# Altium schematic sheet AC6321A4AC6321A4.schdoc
size 127 x 101 mm
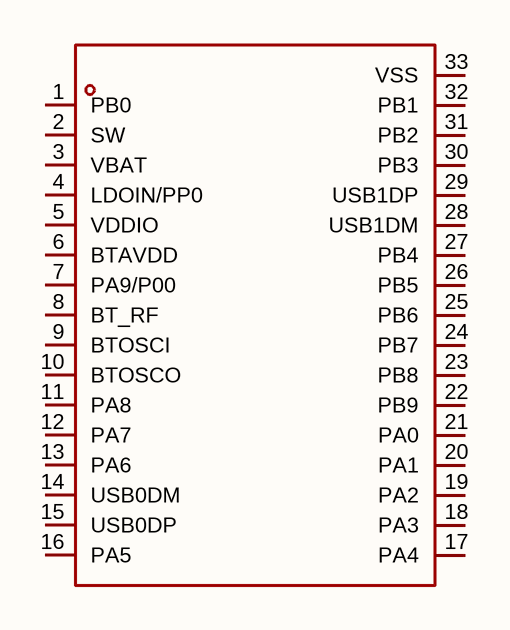
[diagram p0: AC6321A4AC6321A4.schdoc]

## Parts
U?  ac6321a4  [QFN-32_L4.0-W4.0-P0.40-TL-EP2.7]  (value not drawn)

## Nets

Not connected (* = marked no-connect by the designer): U? 1(PB0) 2(SW) 3(VBAT) 4(LDOIN/PP0) 5(VDDIO) 6(BTAVDD) 7(PA9/P00) 8(BT_RF) 9(BTOSCI) 10(BTOSCO) 11(PA8) 12(PA7) 13(PA6) 14(USB0DM) 15(USB0DP) 16(PA5) 17(PA4) 18(PA3) 19(PA2) 20(PA1) 21(PA0) 22(PB9) 23(PB8) 24(PB7) 25(PB6) 26(PB5) 27(PB4) 28(USB1DM) 29(USB1DP) 30(PB3) 31(PB2) 32(PB1) 33(VSS)

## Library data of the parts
U? = ac6321a4: Manufacturer: JL(杰理); AddInBom: yes; ModelId: 1e9eca8b25044b9fa4f766d7d1391f8f; ModelTransform: 158.267,158.267,0,0,0,0,0,0,0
